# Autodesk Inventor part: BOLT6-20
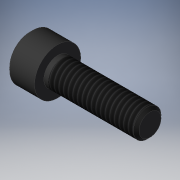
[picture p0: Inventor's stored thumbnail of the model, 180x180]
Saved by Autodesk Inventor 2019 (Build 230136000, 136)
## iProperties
Created: 2022-11
Part Number: BOLT6-20
Material: Generic
Catalog Web Link: www.cadenas.de
Description: BOLT-Hexagon Socket Head Cap Screws
Vendor: MISUMI
Document SubType Name: Modeling
Designer: psAdmin
Manufacturer: MISUMI
Mass: 0.958655 g
Surface Area: 7.56446 cm^2
Volume: 0.958655 cm^3
Density: 1 g/cm^3
Appearance: PSOLRGB-175-175-175
Category: PARTsolutions
Company: MISUMI
Title: BOLT6-20
Author: Cadenas PARTsolutions
Comments: Hexagon Socket Head Cap Screws
PSOL_IDENT_0: {$CADENAS_DATA/23d-libs/misumi/metric/accessories/bolt.prj},157 {VTYP=3D},{NB=BOLT6-20},{LINA=BOLT6-
PSOL_IDENT_1: 20},{NN=BOLT},{DATE=30.06.2021 13:30:08},{GEOMDATE=12.05.2017 08:21:09},{VERSION=},{LINEID=120},{WBV
PSOL_IDENT_2: AR=L},{WBNUMERIC=L}  {NB=BOLT6-20},{LINA=BOLT6-20},{KT=DUMMY},{PN=BOLT6-20},{TYPE=BOLT},{L=20.0},{M=
PSOL_IDENT_3: 6.0},{P=1},{A=10.0},{E=6.0},{B=5.0},{C=0.60},{LL=0}
NB: BOLT6-20
NN: BOLT
NT: Hexagon Socket Head Cap Screws
NBSYN: $PN.
LINA: BOLT6-20
CATALOG: Misumi
PN: BOLT6-20
L: 20
M: 6
P: 1
C: 0.6
SUPPLIER: MISUMI
ARTICLENO: BOLT6-20
BOMINFO: BOLT6-20
CREATOR: CADENAS GmbH
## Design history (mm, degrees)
sketch "Sketch_1"
  geometry: L1 (20, 0)-(-6, 0); L2 (-6, 0)-(-6, 4.4); L3 (-6, 4.4)-(-5.4, 5); L4 (-5.4, 5)-(0, 5); L5 (0, 5)-(0, 3); L6 (0, 3)-(19.387, 3); L7 (19.387, 3)-(20, 2.386); L8 (20, 2.386)-(20, 0); L9 (20, 0)-(-6, 0)
  constraints: 18 end point
revolve "Revolution1" sketch "Sketch_1" stored, may be unused: angle "d0" = 360 deg
thread "Thread1" dims "d1" = 18.3865, "d2" = 0
sketch "Sketch2"
  geometry: 1 further point
hole "Hole1" sketch "Sketch2" at (0, 0) diameter "d3" = 5; stored, may be unused: countersink angle "d7" = 90 deg, drill point angle "d9" = 150 deg; dims "d4" = 6, "d5" = 4, "d6" = 2, "d8" = 3
sketch "Sketch_3"
  geometry: L1 (-2.5, -1.443)-(0, -2.887); L2 (0, -2.887)-(2.5, -1.443); L3 (2.5, -1.443)-(2.5, 1.443); L4 (2.5, 1.443)-(0, 2.887); L5 (0, 2.887)-(-2.5, 1.443); L6 (-2.5, 1.443)-(-2.5, -1.443)
  constraints: 12 end point
extrude "Extrusion1" cut sketch "Sketch_3" distance "d10" = 3; taper "d11" = 0 deg
node "to_cp_XY"
node "to_cp_YZ"
node "to_cp_ZX"
node "to_cp_X"
node "to_cp_Y"
node "to_cp_Z"
node "to_cp_Center"
body "Solid1"
other parameters: "d12" = 0
